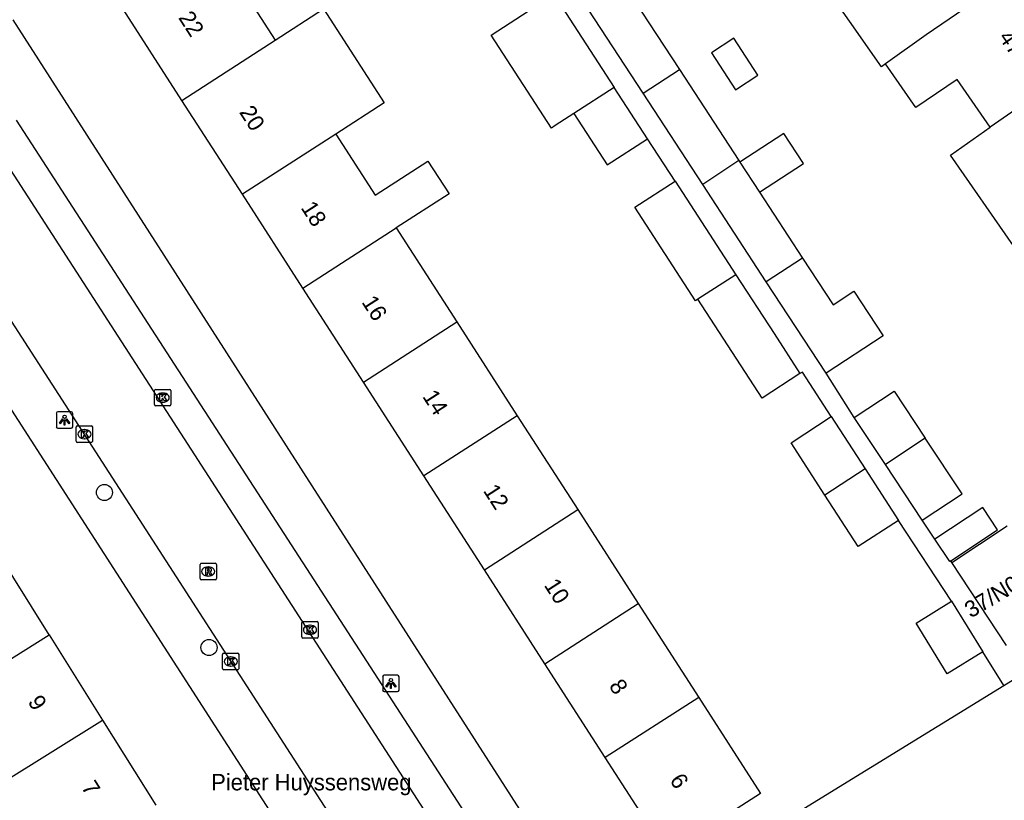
# Model space of a CAD drawing. Extents: x 159353 to 160616, y 385893 to 387321.
# Drawn here: x 159807.5 to 159867.4, y 386198.4 to 386245.9 of the extents above; entities that cross this region are included whole.
import ezdxf

# ---------------------------------------------------------------- set-up
doc = ezdxf.new("R2010")
doc.units = 0
for name, color, linetype in [('IMGEO_Boom', 7, 'Continuous'), ('IMGEO_Kolk', 7, 'Continuous'), ('IMGEO_Lichtpunt', 7, 'Continuous'), ('IMGEO_Openbare_ruimte_label', 7, 'Continuous'), ('IMGEO_Pand', 7, 'Continuous'), ('IMGEO_Pand_nummerreeks', 7, 'Continuous'), ('IMGEO_Rijbaan_lokaal_open', 7, 'Continuous'), ('IMGEO_Rioolput', 7, 'Continuous'), ('IMGEO_Voetpad_open', 7, 'Continuous')]:
    doc.layers.add(name, color=color, linetype=linetype)

msp = doc.modelspace()

# ---------------------------------------------------------------- linework, layer by layer
at = {"layer": 'IMGEO_Boom'}
for centre in [(159812.703, 386217.126), (159819.064, 386207.692)]:
    msp.add_circle(centre, 0.489, dxfattribs=at)
at = {"layer": 'IMGEO_Kolk'}
for p, q in [((159815.748, 386222.471), (159815.748, 386223.323)), ((159815.823, 386223.397), (159816.675, 386223.397)), ((159816.236, 386223.177), (159816.261, 386223.177)), ((159816.749, 386223.323), (159816.749, 386222.471)), ((159816.675, 386222.397), (159815.823, 386222.397)), ((159816.259, 386222.617), (159816.234, 386222.617)), ((159811.061, 386221.175), (159811.913, 386221.175)), ((159810.986, 386220.249), (159810.986, 386221.101)), ((159811.474, 386220.955), (159811.499, 386220.955)), ((159811.987, 386221.101), (159811.987, 386220.249)), ((159811.913, 386220.175), (159811.061, 386220.175)), ((159811.497, 386220.395), (159811.472, 386220.395)), ((159824.706, 386208.342), (159824.706, 386209.194)), ((159824.781, 386209.268), (159825.633, 386209.268)), ((159825.707, 386209.194), (159825.707, 386208.342)), ((159825.194, 386209.048), (159825.219, 386209.048)), ((159825.633, 386208.268), (159824.781, 386208.268)), ((159825.217, 386208.488), (159825.192, 386208.488)), ((159819.962, 386207.345), (159820.814, 386207.345)), ((159819.887, 386206.419), (159819.887, 386207.271)), ((159820.375, 386207.125), (159820.4, 386207.125)), ((159820.888, 386207.271), (159820.888, 386206.419)), ((159820.814, 386206.345), (159819.962, 386206.345)), ((159820.398, 386206.565), (159820.373, 386206.565))]:
    msp.add_line(p, q, dxfattribs=at)
for points in [[(159815.748, 386222.471), (159815.748, 386223.323)], [(159815.823, 386223.397), (159816.675, 386223.397)], [(159816.069, 386223.097), (159816.192, 386223.097), (159816.192, 386222.946), (159816.322, 386223.097), (159816.486, 386223.097), (159816.34, 386222.946), (159816.493, 386222.697), (159816.341, 386222.697), (159816.256, 386222.861), (159816.192, 386222.794), (159816.192, 386222.697), (159816.069, 386222.697), (159816.069, 386223.097)], [(159816.749, 386223.323), (159816.749, 386222.471)], [(159816.675, 386222.397), (159815.823, 386222.397)], [(159811.061, 386221.175), (159811.913, 386221.175)], [(159810.986, 386220.249), (159810.986, 386221.101)], [(159811.307, 386220.875), (159811.43, 386220.875), (159811.43, 386220.724), (159811.56, 386220.875), (159811.724, 386220.875), (159811.578, 386220.724), (159811.731, 386220.475), (159811.579, 386220.475), (159811.494, 386220.639), (159811.43, 386220.572), (159811.43, 386220.475), (159811.307, 386220.475), (159811.307, 386220.875)], [(159811.987, 386221.101), (159811.987, 386220.249)], [(159811.913, 386220.175), (159811.061, 386220.175)], [(159824.706, 386208.342), (159824.706, 386209.194)], [(159824.781, 386209.268), (159825.633, 386209.268)], [(159825.707, 386209.194), (159825.707, 386208.342)], [(159825.027, 386208.968), (159825.15, 386208.968), (159825.15, 386208.817), (159825.28, 386208.968), (159825.444, 386208.968), (159825.298, 386208.817), (159825.451, 386208.568), (159825.299, 386208.568), (159825.214, 386208.732), (159825.15, 386208.665), (159825.15, 386208.568), (159825.027, 386208.568), (159825.027, 386208.968)], [(159825.633, 386208.268), (159824.781, 386208.268)], [(159819.962, 386207.345), (159820.814, 386207.345)], [(159819.887, 386206.419), (159819.887, 386207.271)], [(159820.208, 386207.045), (159820.331, 386207.045), (159820.331, 386206.894), (159820.461, 386207.045), (159820.625, 386207.045), (159820.479, 386206.894), (159820.632, 386206.645), (159820.48, 386206.645), (159820.395, 386206.809), (159820.331, 386206.742), (159820.331, 386206.645), (159820.208, 386206.645), (159820.208, 386207.045)], [(159820.888, 386207.271), (159820.888, 386206.419)], [(159820.814, 386206.345), (159819.962, 386206.345)]]:
    msp.add_lwpolyline(points, dxfattribs=at)
for centre, start, end in [((159815.825, 386223.321), 91.55205, 178.44795), ((159815.825, 386223.321), 91.55205, 178.44795), ((159816.673, 386223.321), 1.55205, 88.44795), ((159816.673, 386223.321), 1.55205, 88.44795), ((159815.825, 386222.473), 181.55205, 268.44795), ((159815.825, 386222.473), 181.55205, 268.44795), ((159816.673, 386222.473), 271.55205, 358.44795), ((159816.673, 386222.473), 271.55205, 358.44795), ((159811.063, 386221.099), 91.55205, 178.44795), ((159811.063, 386221.099), 91.55205, 178.44795), ((159811.911, 386221.099), 1.55205, 88.44795), ((159811.911, 386221.099), 1.55205, 88.44795), ((159811.063, 386220.251), 181.55205, 268.44795), ((159811.063, 386220.251), 181.55205, 268.44795), ((159811.911, 386220.251), 271.55205, 358.44795), ((159811.911, 386220.251), 271.55205, 358.44795), ((159824.783, 386209.192), 91.55205, 178.44795), ((159824.783, 386209.192), 91.55205, 178.44795), ((159825.631, 386209.192), 1.55205, 88.44795), ((159825.631, 386209.192), 1.55205, 88.44795), ((159824.783, 386208.344), 181.55205, 268.44795), ((159824.783, 386208.344), 181.55205, 268.44795), ((159825.631, 386208.344), 271.55205, 358.44795), ((159825.631, 386208.344), 271.55205, 358.44795), ((159819.964, 386207.269), 91.55205, 178.44795), ((159819.964, 386207.269), 91.55205, 178.44795), ((159820.812, 386207.269), 1.55205, 88.44795), ((159820.812, 386207.269), 1.55205, 88.44795), ((159819.964, 386206.421), 181.55205, 268.44795), ((159819.964, 386206.421), 181.55205, 268.44795), ((159820.812, 386206.421), 271.55205, 358.44795), ((159820.812, 386206.421), 271.55205, 358.44795)]:
    msp.add_arc(centre, 0.0765, start, end, dxfattribs=at)
for centre, major_axis, ratio, start_param, end_param in [((159816.235, 386222.897), (-0.387, 0.002), 0.722429, 4.712389, 7.853982), ((159816.26, 386222.897), (-0.39, 0.002), 0.717154, 1.570796, 4.712389), ((159811.473, 386220.675), (-0.387, 0.002), 0.722429, 4.712389, 7.853982), ((159811.498, 386220.675), (-0.39, 0.002), 0.717154, 1.570796, 4.712389), ((159825.193, 386208.768), (-0.387, 0.002), 0.722429, 4.712389, 7.853982), ((159825.218, 386208.768), (-0.39, 0.002), 0.717154, 1.570796, 4.712389), ((159820.374, 386206.845), (-0.387, 0.002), 0.722429, 4.712389, 7.853982), ((159820.399, 386206.845), (-0.39, 0.002), 0.717154, 1.570796, 4.712389)]:
    msp.add_ellipse(centre, major_axis=major_axis, ratio=ratio, start_param=start_param, end_param=end_param, dxfattribs=at)
at = {"layer": 'IMGEO_Lichtpunt'}
for p, q in [((159809.778, 386221.935), (159809.778, 386221.128)), ((159809.778, 386221.935), (159809.778, 386221.128)), ((159810.68, 386222.03), (159809.872, 386222.03)), ((159810.68, 386222.03), (159809.872, 386222.03)), ((159810.774, 386221.128), (159810.774, 386221.935)), ((159810.774, 386221.128), (159810.774, 386221.935)), ((159809.872, 386221.034), (159810.68, 386221.034)), ((159809.872, 386221.034), (159810.68, 386221.034)), ((159829.627, 386205.913), (159829.627, 386205.106)), ((159829.627, 386205.913), (159829.627, 386205.106)), ((159830.529, 386206.008), (159829.721, 386206.008)), ((159830.529, 386206.008), (159829.721, 386206.008)), ((159830.623, 386205.106), (159830.623, 386205.913)), ((159830.623, 386205.106), (159830.623, 386205.913)), ((159829.721, 386205.012), (159830.529, 386205.012)), ((159829.721, 386205.012), (159830.529, 386205.012))]:
    msp.add_line(p, q, dxfattribs=at)
for points in [[(159810.152, 386221.599), (159810.191, 386221.571), (159810.003, 386221.309), (159809.965, 386221.336), (159810.152, 386221.599)], [(159810.254, 386221.551), (159810.301, 386221.551), (159810.301, 386221.229), (159810.254, 386221.229), (159810.254, 386221.551)], [(159810.364, 386221.571), (159810.402, 386221.598), (159810.589, 386221.336), (159810.55, 386221.308), (159810.364, 386221.571)], [(159830.001, 386205.577), (159830.04, 386205.549), (159829.852, 386205.287), (159829.814, 386205.314), (159830.001, 386205.577)], [(159830.213, 386205.549), (159830.251, 386205.576), (159830.438, 386205.314), (159830.399, 386205.286), (159830.213, 386205.549)], [(159830.103, 386205.529), (159830.15, 386205.529), (159830.15, 386205.207), (159830.103, 386205.207), (159830.103, 386205.529)]]:
    msp.add_lwpolyline(points, dxfattribs=at)
for centre in [(159810.277, 386221.733), (159830.126, 386205.711)]:
    msp.add_circle(centre, 0.0994, dxfattribs=at)
for centre, start, end in [((159809.872, 386221.935), 90, 180), ((159809.872, 386221.935), 90, 180), ((159810.68, 386221.935), 0, 90), ((159810.68, 386221.935), 0, 90), ((159809.872, 386221.128), 180, 270), ((159809.872, 386221.128), 180, 270), ((159810.68, 386221.128), 270, 0), ((159810.68, 386221.128), 270, 360), ((159829.721, 386205.913), 90, 180), ((159829.721, 386205.913), 90, 180), ((159830.529, 386205.913), 0, 90), ((159830.529, 386205.913), 0, 90), ((159829.721, 386205.106), 180, 270), ((159829.721, 386205.106), 180, 270), ((159830.529, 386205.106), 270, 0), ((159830.529, 386205.106), 270, 360)]:
    msp.add_arc(centre, 0.0946, start, end, dxfattribs=at)
at = {"layer": 'IMGEO_Pand'}
for points in [[(159817.416, 386240.979), (159813.655, 386246.817), (159816.177, 386248.442), (159815.173, 386250), (159813.989, 386251.839), (159818.613, 386254.818), (159820.943, 386251.204), (159819.478, 386250.26), (159819.646, 386250), (159823.098, 386244.641)], [(159860.22, 386243.199), (159859.962, 386243.015), (159856.068, 386248.607), (159858.552, 386250.337)], [(159868.273, 386248.807), (159862.69, 386244.961), (159860.22, 386243.199)], [(159843.996, 386248.494), (159847.677, 386242.856)], [(159841.26, 386240.183), (159840.117, 386239.446), (159839.887, 386239.298), (159836.219, 386244.955), (159840.042, 386247.435)], [(159840.042, 386247.435), (159843.718, 386241.767)], [(159845.472, 386241.416), (159841.79, 386247.054)], [(159823.098, 386244.641), (159826.024, 386246.548), (159829.714, 386240.823), (159826.777, 386238.93)], [(159817.416, 386240.979), (159823.098, 386244.641)], [(159852.446, 386242.514), (159850.98, 386244.76), (159849.63, 386243.878), (159851.096, 386241.632), (159852.446, 386242.514)], [(159845.472, 386241.416), (159847.677, 386242.856)], [(159847.677, 386242.856), (159851.285, 386237.331)], [(159866.587, 386239.358), (159864.574, 386242.252), (159862.059, 386240.556), (159860.22, 386243.199)], [(159872.166, 386243.219), (159866.587, 386239.358)], [(159843.718, 386241.767), (159841.26, 386240.183)], [(159845.744, 386238.643), (159843.718, 386241.767)], [(159821.095, 386235.267), (159817.416, 386240.979)], [(159849.093, 386235.871), (159845.472, 386241.416)], [(159841.26, 386240.183), (159843.291, 386237.052), (159845.744, 386238.643)], [(159870.464, 386233.785), (159867.994, 386232.122), (159864.156, 386237.639), (159866.587, 386239.358)], [(159826.777, 386238.93), (159821.095, 386235.267)], [(159826.777, 386238.93), (159829.166, 386235.22), (159832.38, 386237.292), (159833.67, 386235.29), (159830.456, 386233.218)], [(159852.555, 386235.387), (159855.231, 386237.135), (159854.034, 386238.969), (159851.357, 386237.221)], [(159851.285, 386237.331), (159849.093, 386235.871)], [(159851.285, 386237.331), (159851.357, 386237.221)], [(159851.357, 386237.221), (159852.555, 386235.387)], [(159848.806, 386228.881), (159848.654, 386228.783), (159844.958, 386234.482), (159847.415, 386236.067)], [(159847.415, 386236.067), (159851.112, 386230.367)], [(159852.961, 386229.948), (159849.093, 386235.871)], [(159824.774, 386229.555), (159821.095, 386235.267)], [(159852.555, 386235.387), (159855.166, 386231.388)], [(159824.774, 386229.555), (159830.456, 386233.218)], [(159830.456, 386233.218), (159834.136, 386227.506)], [(159855.166, 386231.388), (159852.961, 386229.948)], [(159855.166, 386231.388), (159857.022, 386228.546), (159858.288, 386229.374), (159860.069, 386226.647), (159856.597, 386224.379)], [(159851.112, 386230.367), (159848.806, 386228.881)], [(159851.112, 386230.367), (159853.432, 386226.79), (159855.01, 386224.357)], [(159828.454, 386223.843), (159824.774, 386229.555)], [(159856.597, 386224.379), (159852.961, 386229.948)], [(159855.01, 386224.357), (159852.709, 386222.865), (159848.806, 386228.881)], [(159828.454, 386223.843), (159834.136, 386227.506)], [(159834.136, 386227.506), (159837.815, 386221.795)], [(159832.133, 386218.132), (159828.454, 386223.843)], [(159858.313, 386221.689), (159860.733, 386223.291), (159862.622, 386220.437)], [(159837.815, 386221.795), (159832.133, 386218.132)], [(159837.815, 386221.795), (159841.494, 386216.083)], [(159856.53, 386216.969), (159854.468, 386220.155), (159856.914, 386221.738)], [(159856.914, 386221.738), (159858.966, 386218.567)], [(159860.203, 386218.835), (159858.313, 386221.689)], [(159862.622, 386220.437), (159860.203, 386218.835)], [(159862.451, 386215.439), (159864.871, 386217.041), (159862.622, 386220.437)], [(159862.451, 386215.439), (159860.203, 386218.835)], [(159835.812, 386212.42), (159832.133, 386218.132)], [(159858.966, 386218.567), (159856.53, 386216.969)], [(159858.966, 386218.567), (159860.999, 386215.43)], [(159860.999, 386215.43), (159858.551, 386213.846), (159856.53, 386216.969)], [(159835.812, 386212.42), (159841.494, 386216.083)], [(159841.494, 386216.083), (159845.174, 386210.371)], [(159864.185, 386212.965), (159867.031, 386214.85), (159866.131, 386216.208), (159863.218, 386214.28)], [(159864.248, 386212.87), (159867.604, 386215.088)], [(159864.185, 386212.965), (159864.118, 386212.921), (159863.218, 386214.28)], [(159809.339, 386208.458), (159806.098, 386213.64)], [(159867.581, 386207.825), (159864.248, 386212.87)], [(159839.491, 386206.708), (159835.812, 386212.42)], [(159839.491, 386206.708), (159845.174, 386210.371)], [(159845.174, 386210.371), (159848.853, 386204.66)], [(159866.139, 386207.439), (159863.971, 386206.096), (159862.068, 386209.169), (159864.234, 386210.517)], [(159864.234, 386210.517), (159866.139, 386207.439)], [(159800.727, 386203.064), (159803.152, 386204.589), (159809.339, 386208.458)], [(159809.339, 386208.458), (159812.581, 386203.275)], [(159843.17, 386200.997), (159839.491, 386206.708)], [(159848.853, 386204.66), (159852.616, 386198.818), (159846.932, 386195.157), (159843.17, 386200.997)], [(159848.853, 386204.66), (159843.17, 386200.997)], [(159806.387, 386199.403), (159812.581, 386203.275)], [(159812.581, 386203.275), (159815.821, 386198.094)]]:
    msp.add_lwpolyline(points, dxfattribs=at)
at = {"layer": 'IMGEO_Rijbaan_lokaal_open'}
for points in [[(159867.411, 386205.386), (159868.623, 386206.132)], [(159842.817, 386190.245), (159867.411, 386205.386)]]:
    msp.add_lwpolyline(points, dxfattribs=at)
at = {"layer": 'IMGEO_Rioolput'}
for p, q in [((159818.517, 386211.89), (159818.517, 386212.742)), ((159818.592, 386212.816), (159819.444, 386212.816)), ((159819.518, 386212.742), (159819.518, 386211.89)), ((159819.005, 386212.596), (159819.03, 386212.596)), ((159819.444, 386211.816), (159818.592, 386211.816)), ((159819.028, 386212.036), (159819.003, 386212.036))]:
    msp.add_line(p, q, dxfattribs=at)
for points in [[(159818.517, 386211.89), (159818.517, 386212.742)], [(159818.592, 386212.816), (159819.444, 386212.816)], [(159819.518, 386212.742), (159819.518, 386211.89)], [(159819.106, 386212.514), (159818.854, 386212.516), (159818.854, 386212.116)], [(159818.854, 386212.116), (159818.978, 386212.116), (159818.978, 386212.278), (159818.989, 386212.278)], [(159819.032, 386212.435), (159818.978, 386212.435), (159818.978, 386212.354)], [(159818.978, 386212.354), (159819.03, 386212.354)], [(159819.036, 386212.249), (159819.107, 386212.116), (159819.247, 386212.116), (159819.182, 386212.242)], [(159819.444, 386211.816), (159818.592, 386211.816)]]:
    msp.add_lwpolyline(points, dxfattribs=at)
for centre, radius, start, end in [((159818.594, 386212.74), 0.0765, 91.55205, 178.44795), ((159818.594, 386212.74), 0.0765, 91.55205, 178.44795), ((159819.442, 386212.74), 0.0765, 1.55205, 88.44795), ((159819.442, 386212.74), 0.0765, 1.55205, 88.44795), ((159818.988, 386212.225), 0.0533, 26.02933, 88.69889), ((159819.014, 386212.543), 0.19, 274.7715, 282.96867), ((159819.038, 386212.339), 0.0964, 77.00612, 93.18647), ((159819.052, 386212.396), 0.0378, 276.66336, 79.67722), ((159819.105, 386212.404), 0.109, 350.36119, 89.41601), ((159819.103, 386212.404), 0.112, 277.58423, 350.98172), ((159819.087, 386212.189), 0.108, 29.51342, 73.79051), ((159818.594, 386211.892), 0.0765, 181.55205, 268.44795), ((159818.594, 386211.892), 0.0765, 181.55205, 268.44795), ((159819.442, 386211.892), 0.0765, 271.55205, 358.44795), ((159819.442, 386211.892), 0.0765, 271.55205, 358.44795)]:
    msp.add_arc(centre, radius, start, end, dxfattribs=at)
for centre, major_axis, ratio, start_param, end_param in [((159819.004, 386212.316), (-0.387, 0.002), 0.722429, 4.712389, 7.853982), ((159819.029, 386212.316), (-0.39, 0.002), 0.717154, 1.570796, 4.712389)]:
    msp.add_ellipse(centre, major_axis=major_axis, ratio=ratio, start_param=start_param, end_param=end_param, dxfattribs=at)
at = {"layer": 'IMGEO_Voetpad_open'}
for points in [[(159807.126, 386245.89), (159842.817, 386190.245)], [(159804.207, 386241.004), (159837.82, 386189.003)], [(159793.173, 386240.363), (159795.649, 386239.796), (159831.974, 386183.449)], [(159807.339, 386239.784), (159837.799, 386192.71)], [(159847.415, 386236.067), (159845.744, 386238.643)], [(159833.027, 386187.288), (159800.096, 386238.294)], [(159856.914, 386221.738), (159855.157, 386224.453), (159855.01, 386224.357)], [(159858.313, 386221.689), (159856.597, 386224.379)], [(159864.234, 386210.517), (159860.999, 386215.43)], [(159863.218, 386214.28), (159862.451, 386215.439)], [(159864.248, 386212.87), (159864.185, 386212.965)], [(159867.411, 386205.386), (159866.139, 386207.439)]]:
    msp.add_lwpolyline(points, dxfattribs=at)

# ---------------------------------------------------------------- texts
at = {"layer": 'IMGEO_Openbare_ruimte_label'}
msp.add_text('Pieter Huyssensweg', height=1, dxfattribs=at).set_placement((159819.194, 386199.002))
at = {"layer": 'IMGEO_Pand_nummerreeks'}
for s, rotation, p in [('22', 302.78777, (159817.173, 386246.008)), ('47', 304.86386, (159867.057, 386244.815)), ('20', 302.78777, (159820.874, 386240.263)), ('18', 302.79016, (159824.621, 386234.447)), ('16', 302.78777, (159828.316, 386228.709)), ('14', 302.78777, (159832.013, 386222.969)), ('12', 302.78777, (159835.71, 386217.232)), ('37/N01', 30.53865, (159865.402, 386209.458)), ('10', 302.78777, (159839.41, 386211.487)), ('8', 302.78777, (159843.358, 386205.359)), ('9', 302.02331, (159808.013, 386204.394)), ('7', 302.02331, (159811.264, 386199.195)), ('6', 302.78777, (159847.052, 386199.622))]:
    msp.add_text(s, height=1, rotation=rotation, dxfattribs=at).set_placement(p)

doc.saveas('drawing.dxf')
